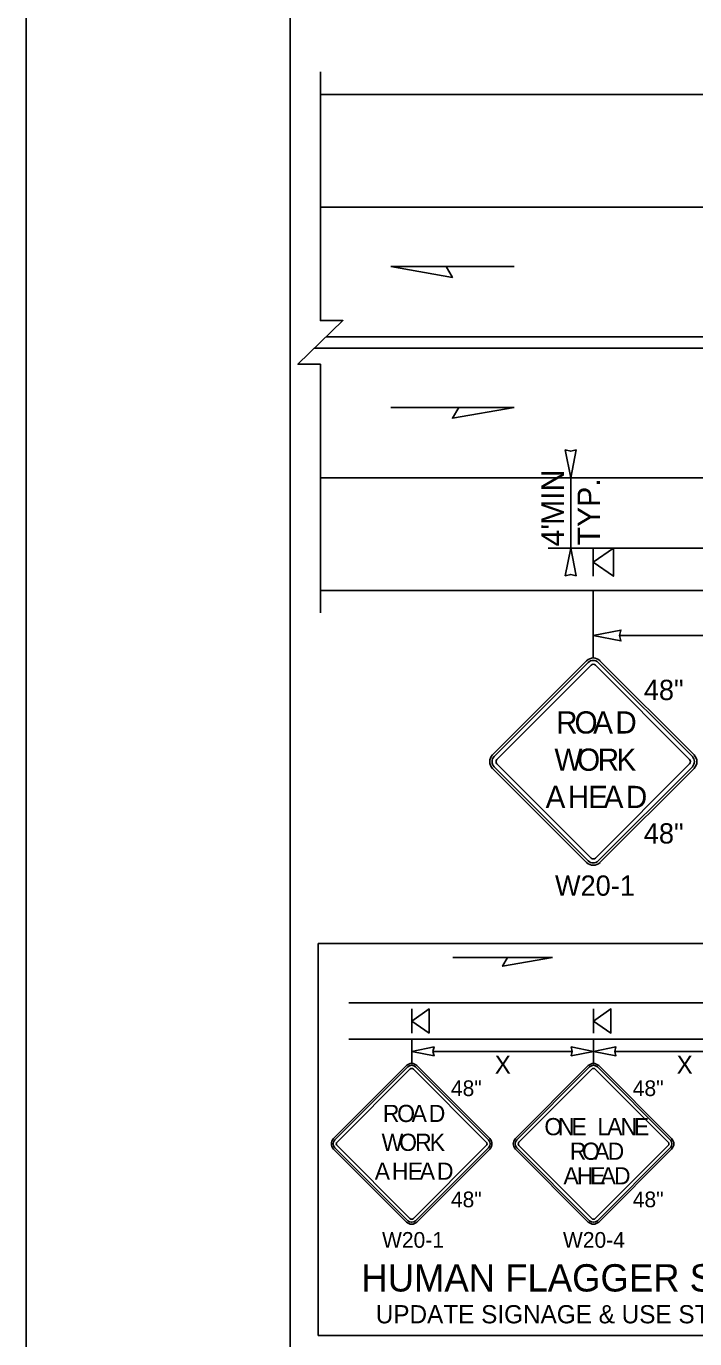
# Model space of a CAD drawing. Extents: x 99999.1 to 100095.7, y 99995 to 100010.7.
# Drawn here: x 99999.062 to 100001.437, y 100003.076 to 100007.734 of the extents above; entities that cross this region are included whole.
import ezdxf

# ---------------------------------------------------------------- set-up
doc = ezdxf.new("R2010")
doc.units = 0
for name, color, linetype in [('RD_ED_ShoulderPavedEdge', 7, 'Continuous'), ('RD_MK_LineDblYellowCenter', 7, 'Continuous'), ('RD_MK_LineEdgeWhite', 7, 'Continuous'), ('SH_DE_DetailHeading2Text', 7, 'Continuous'), ('SH_GI_PlotLimits', 7, 'Continuous'), ('SH_GI_SheetBorder', 7, 'Continuous'), ('TR_SN_ConstructionSigns', 7, 'Continuous'), ('TR_WZ_PortableSignMountBlk-Org', 7, 'Continuous'), ('TR_WZ_WorkZoneDetails', 7, 'Continuous'), ('TR_WZ_WorkZoneTextCurrent', 7, 'Continuous')]:
    doc.layers.add(name, color=color, linetype=linetype)

msp = doc.modelspace()

# ---------------------------------------------------------------- linework, layer by layer
at = {"layer": 'RD_ED_ShoulderPavedEdge'}
for p, q in [((100000.1076, 100007.4923), (100015.6424, 100007.4923)), ((100000.1076, 100005.7323), (100015.6424, 100005.7323)), ((100000.2089, 100004.1394), (100003.1825, 100004.1394))]:
    msp.add_line(p, q, dxfattribs=at)
at = {"layer": 'RD_MK_LineDblYellowCenter'}
for p, q in [((100000.1282, 100006.6323), (100003.4767, 100006.6323)), ((100000.0869, 100006.5923), (100003.4767, 100006.5923))]:
    msp.add_line(p, q, dxfattribs=at)
at = {"layer": 'RD_MK_LineEdgeWhite'}
for p, q in [((100000.1076, 100007.0923), (100015.6424, 100007.0923)), ((100000.1076, 100006.1323), (100015.6424, 100006.1323)), ((100000.2089, 100004.2685), (100003.1825, 100004.2685))]:
    msp.add_line(p, q, dxfattribs=at)
at = {"layer": 'SH_GI_PlotLimits'}
msp.add_lwpolyline([(99999.0625, 99999.6875), (100016.0625, 99999.6875), (100016.0625, 100010.6875), (99999.0625, 100010.6875)], close=True, dxfattribs=at)
at = {"layer": 'SH_GI_SheetBorder'}
msp.add_line((100000, 100010.375), (100000, 100000), dxfattribs=at)
at = {"layer": 'TR_SN_ConstructionSigns'}
for p, q in [((100001.0528, 100005.4824), (100000.7187, 100005.1483)), ((100001.4346, 100005.1483), (100001.1005, 100005.4824)), ((100001.0588, 100005.4765), (100000.7246, 100005.1424)), ((100000.7346, 100005.1324), (100001.0687, 100005.4665)), ((100001.0846, 100005.4665), (100001.4187, 100005.1324)), ((100001.4287, 100005.1424), (100001.0945, 100005.4765)), ((100000.7246, 100005.1066), (100001.0588, 100004.7725)), ((100001.0687, 100004.7824), (100000.7346, 100005.1165)), ((100001.4187, 100005.1165), (100001.0846, 100004.7824)), ((100001.0945, 100004.7725), (100001.4287, 100005.1066)), ((100000.7187, 100005.1006), (100001.0528, 100004.7665)), ((100001.1005, 100004.7665), (100001.4346, 100005.1006)), ((100000.4132, 100004.0456), (100000.1542, 100003.7866)), ((100000.4178, 100004.0409), (100000.1588, 100003.782)), ((100000.1665, 100003.7743), (100000.4255, 100004.0332)), ((100000.4378, 100004.0332), (100000.6968, 100003.7743)), ((100000.7045, 100003.782), (100000.4455, 100004.0409)), ((100000.7091, 100003.7866), (100000.4502, 100004.0456)), ((100001.0591, 100004.0456), (100000.8001, 100003.7866)), ((100001.0637, 100004.0409), (100000.8048, 100003.782)), ((100000.8125, 100003.7743), (100001.0714, 100004.0332)), ((100001.0838, 100004.0332), (100001.3427, 100003.7743)), ((100001.3504, 100003.782), (100001.0915, 100004.0409)), ((100001.3551, 100003.7866), (100001.0961, 100004.0456)), ((100000.1588, 100003.7542), (100000.4178, 100003.4952)), ((100000.4255, 100003.503), (100000.1665, 100003.7619)), ((100000.6968, 100003.7619), (100000.4378, 100003.503)), ((100000.4455, 100003.4952), (100000.7045, 100003.7542)), ((100000.8048, 100003.7542), (100001.0637, 100003.4952)), ((100001.0714, 100003.503), (100000.8125, 100003.7619)), ((100001.3427, 100003.7619), (100001.0838, 100003.503)), ((100001.0915, 100003.4952), (100001.3504, 100003.7542)), ((100000.1542, 100003.7496), (100000.4132, 100003.4906)), ((100000.4502, 100003.4906), (100000.7091, 100003.7496)), ((100000.8001, 100003.7496), (100001.0591, 100003.4906)), ((100001.0961, 100003.4906), (100001.3551, 100003.7496))]:
    msp.add_line(p, q, dxfattribs=at)
for centre, radius, start, end in [((100001.0767, 100005.4586), 0.0338, 45, 135), ((100001.0767, 100005.4586), 0.0253, 45, 135), ((100001.0767, 100005.4586), 0.0113, 45, 135), ((100000.7425, 100005.1245), 0.0338, 135, 225), ((100000.7425, 100005.1245), 0.0253, 135, 225), ((100000.7425, 100005.1245), 0.0113, 135, 225), ((100001.4108, 100005.1245), 0.0113, 315, 45), ((100001.4108, 100005.1245), 0.0253, 315, 45), ((100001.4108, 100005.1245), 0.0338, 315, 45), ((100001.0767, 100004.7904), 0.0113, 225, 315), ((100001.0767, 100004.7904), 0.0338, 225, 315), ((100001.0767, 100004.7904), 0.0253, 225, 315), ((100000.4317, 100004.0271), 0.0262, 45, 135), ((100000.4317, 100004.0271), 0.0196, 45, 135), ((100000.4317, 100004.0271), 0.00872, 45, 135), ((100001.0776, 100004.0271), 0.0262, 45, 135), ((100001.0776, 100004.0271), 0.0196, 45, 135), ((100001.0776, 100004.0271), 0.00872, 45, 135), ((100000.1727, 100003.7681), 0.0262, 135, 225), ((100000.1727, 100003.7681), 0.0196, 135, 225), ((100000.1727, 100003.7681), 0.00872, 135, 225), ((100000.6906, 100003.7681), 0.00872, 315, 45), ((100000.6906, 100003.7681), 0.0196, 315, 45), ((100000.6906, 100003.7681), 0.0262, 315, 45), ((100000.8186, 100003.7681), 0.0262, 135, 225), ((100000.8186, 100003.7681), 0.0196, 135, 225), ((100000.8186, 100003.7681), 0.00872, 135, 225), ((100001.3366, 100003.7681), 0.00872, 315, 45), ((100001.3366, 100003.7681), 0.0196, 315, 45), ((100001.3366, 100003.7681), 0.0262, 315, 45), ((100000.4317, 100003.5091), 0.0262, 225, 315), ((100000.4317, 100003.5091), 0.0196, 225, 315), ((100000.4317, 100003.5091), 0.00872, 225, 315), ((100001.0776, 100003.5091), 0.0262, 225, 315), ((100001.0776, 100003.5091), 0.0196, 225, 315), ((100001.0776, 100003.5091), 0.00872, 225, 315)]:
    msp.add_arc(centre, radius, start, end, dxfattribs=at)
at = {"layer": 'TR_WZ_PortableSignMountBlk-Org'}
for p, q in [((100001.0767, 100005.7824), (100001.0767, 100005.8824)), ((100000.4317, 100004.1609), (100000.4317, 100004.247)), ((100001.0776, 100004.1609), (100001.0776, 100004.247))]:
    msp.add_line(p, q, dxfattribs=at)
for points in [[(100001.0767, 100005.8323), (100001.1485, 100005.8824), (100001.1485, 100005.7824)], [(100000.4317, 100004.2039), (100000.4935, 100004.247), (100000.4935, 100004.1609)], [(100001.0776, 100004.2039), (100001.1395, 100004.247), (100001.1395, 100004.1609)]]:
    msp.add_lwpolyline(points, close=True, dxfattribs=at)
at = {"layer": 'TR_WZ_WorkZoneDetails'}
for p, q in [((100000.5541, 100006.8816), (100000.7952, 100006.8816)), ((100000.5987, 100006.3816), (100000.3576, 100006.3816)), ((100000.9167, 100006.1323), (100001.0767, 100006.1323)), ((100000.9967, 100005.8824), (100000.9967, 100006.1323)), ((100000.9167, 100005.8824), (100001.0767, 100005.8824)), ((100001.0767, 100005.8824), (100003.4767, 100005.8824)), ((100001.0767, 100005.7326), (100001.0767, 100005.4923)), ((100001.7829, 100005.5723), (100001.1704, 100005.5723)), ((100000.7726, 100004.4292), (100000.578, 100004.4292)), ((100000.4317, 100004.1396), (100000.4317, 100004.0532)), ((100001.0776, 100004.1394), (100001.0776, 100004.0532)), ((100001.0019, 100004.0963), (100000.5073, 100004.0963)), ((100001.6479, 100004.0963), (100001.1533, 100004.0963))]:
    msp.add_line(p, q, dxfattribs=at)
msp.add_lwpolyline([(100000.1076, 100005.6523), (100000.1076, 100006.5349), (100000.0275, 100006.5349), (100000.1876, 100006.6898), (100000.1076, 100006.6898), (100000.1076, 100007.5723)], dxfattribs=at)
for points in [[(100000.3576, 100006.8816), (100000.5764, 100006.843), (100000.5541, 100006.8816)], [(100000.7952, 100006.3816), (100000.5764, 100006.343), (100000.5987, 100006.3816)], [(100000.9967, 100006.1323), (100000.9774, 100006.2306), (100000.9967, 100006.2261), (100001.0159, 100006.2306)], [(100000.9967, 100005.8824), (100000.9774, 100005.7841), (100000.9967, 100005.7887), (100001.0159, 100005.7841)], [(100001.0767, 100005.5723), (100001.1749, 100005.5916), (100001.1704, 100005.5723), (100001.1749, 100005.5531)], [(100000.9313, 100004.4292), (100000.7546, 100004.3981), (100000.7726, 100004.4292)], [(100000.4317, 100004.0963), (100000.511, 100004.1119), (100000.5073, 100004.0963), (100000.511, 100004.0807)], [(100001.0776, 100004.0963), (100000.9982, 100004.1119), (100001.0019, 100004.0963), (100000.9982, 100004.0807)], [(100001.0776, 100004.0963), (100001.157, 100004.1119), (100001.1533, 100004.0963), (100001.157, 100004.0807)]]:
    msp.add_lwpolyline(points, close=True, dxfattribs=at)
at = {"layer": 'TR_WZ_WorkZoneTextCurrent'}
msp.add_lwpolyline([(100000.1, 100004.4792), (100003.2886, 100004.4792), (100003.2886, 100003.0879), (100000.1, 100003.0879)], close=True, dxfattribs=at)

# ---------------------------------------------------------------- texts
at = {"layer": 'SH_DE_DetailHeading2Text'}
msp.add_text('HUMAN FLAGGER SUBSTITUTION', height=0.09689, rotation=360, dxfattribs=at).set_placement((100000.2529, 100003.244))
at = {"layer": 'TR_SN_ConstructionSigns'}
for s, height, p in [('48"', 0.072, (100001.2564, 100005.343)), ('48"', 0.072, (100001.2564, 100004.8339)), ('W20-1', 0.072, (100000.9408, 100004.6486)), ('48"', 0.05581, (100000.571, 100003.9375)), ('48"', 0.05581, (100001.217, 100003.9375)), ('48"', 0.05581, (100000.571, 100003.5429)), ('48"', 0.05581, (100001.217, 100003.5429)), ('W20-1', 0.05581, (100000.3264, 100003.3992)), ('W20-4', 0.05581, (100000.9691, 100003.3992))]:
    msp.add_text(s, height=height, rotation=360, dxfattribs=at).set_placement(p)
for s, height, p in [('R', 0.0788, (100000.9447, 100005.2243)), ('O', 0.0788, (100001.0101, 100005.2243)), ('A', 0.0788, (100001.0763, 100005.2243)), ('D', 0.0788, (100001.155, 100005.2243)), ('W', 0.0788, (100000.9388, 100005.0921)), ('O', 0.0788, (100001.0192, 100005.0921)), ('R', 0.0788, (100001.0924, 100005.0921)), ('K', 0.0788, (100001.1593, 100005.0921)), ('A', 0.0788, (100000.9073, 100004.9599)), ('H', 0.0788, (100000.9861, 100004.9599)), ('E', 0.0788, (100001.0585, 100004.9599)), ('A', 0.0788, (100001.1137, 100004.9599)), ('D', 0.0788, (100001.1924, 100004.9599)), ('R', 0.061, (100000.3294, 100003.8455)), ('O', 0.061, (100000.3801, 100003.8455)), ('A', 0.061, (100000.4314, 100003.8455)), ('D', 0.061, (100000.4924, 100003.8455)), ('O', 0.061, (100000.903, 100003.7986)), ('N', 0.061, (100000.9512, 100003.7986)), ('E', 0.061, (100000.9989, 100003.7986)), ('L', 0.061, (100001.091, 100003.7986)), ('A', 0.061, (100001.1258, 100003.7986)), ('N', 0.061, (100001.1734, 100003.7986)), ('E', 0.061, (100001.221, 100003.7986)), ('W', 0.061, (100000.3248, 100003.743)), ('O', 0.061, (100000.3871, 100003.743)), ('R', 0.061, (100000.4439, 100003.743)), ('K', 0.061, (100000.4958, 100003.743)), ('R', 0.061, (100000.9934, 100003.7114)), ('O', 0.061, (100001.0367, 100003.7114)), ('A', 0.061, (100001.08, 100003.7114)), ('D', 0.061, (100001.1277, 100003.7114)), ('A', 0.061, (100000.3004, 100003.6406)), ('H', 0.061, (100000.3615, 100003.6406)), ('E', 0.061, (100000.4176, 100003.6406)), ('A', 0.061, (100000.4604, 100003.6406)), ('D', 0.061, (100000.5214, 100003.6406)), ('A', 0.061, (100000.9708, 100003.6242)), ('H', 0.061, (100001.0184, 100003.6242)), ('E', 0.061, (100001.066, 100003.6242)), ('A', 0.061, (100001.1026, 100003.6242)), ('D', 0.061, (100001.1502, 100003.6242))]:
    msp.add_text(s, height=height, dxfattribs=at).set_placement(p)
at = {"layer": 'TR_WZ_WorkZoneTextCurrent'}
for s, p in [('MIN', (100000.9727, 100005.9648)), ('TYP.', (100001.1007, 100005.892)), ("4'", (100000.9727, 100005.8883))]:
    msp.add_text(s, height=0.08, rotation=90, dxfattribs=at).set_placement(p)
for s, height, p in [('X', 0.0646, (100000.7266, 100004.0166)), ('X', 0.0646, (100001.3725, 100004.0166)), ('UPDATE SIGNAGE & USE STOP/SLOW PADDLE', 0.064593, (100000.304, 100003.131))]:
    msp.add_text(s, height=height, dxfattribs=at).set_placement(p)

doc.saveas('drawing.dxf')
